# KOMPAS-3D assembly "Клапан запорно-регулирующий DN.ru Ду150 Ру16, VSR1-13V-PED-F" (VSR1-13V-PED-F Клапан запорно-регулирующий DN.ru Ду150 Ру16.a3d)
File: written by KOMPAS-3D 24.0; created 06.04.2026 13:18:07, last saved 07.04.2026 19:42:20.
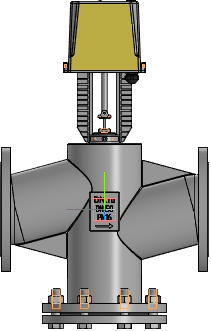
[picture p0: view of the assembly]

Document properties: Автор: R2D2; Полное имя файла: E:\Работа\Зайцев\Солянка\VSR1-13V-PED-F Клапан запорно-регулирующий DN.ru\DN150\исходные материалы\VSR1-13V-PED-F Клапан запорно-регулирующий DN.ru Ду150 Ру16.a3d

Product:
- Component [detail]: Фланец  | qty 2  | pos. 1  | Масса: 7.499952; Автор: R2D2; source file: Фланец.m3d
- Component [detail]: Фланец  | qty 1  | pos. 2  | Масса: 7.499952; Автор: R2D2; source file: Фланец.m3d
- Component [detail]: Корпус  | qty 1  | pos. 3  | Масса: 6.9; Автор: R2D2; source file: Корпус.m3d
- Component [detail]: Электропривод  | qty 1  | pos. 6  | Масса: 0.101125; Автор: R2D2; source file: Электропривод.m3d
- Component [standard]: Болт с шестигранной головкой ГОСТ Р ИСО 4014 - М20 x 80  | qty 8  | Материал: Не определено (density 1000 kg/m3); Масса: 0.2712; Раздел спецификации: Стандартные изделия; Рассекать на разрезах: no; additional columns: ГОСТ Р ИСО 4014-2013
- Component [standard]: Гайка М20-6H ГОСТ 5915-70  | qty 8  | Масса: 0.07144; Раздел спецификации: Стандартные изделия; Рассекать на разрезах: no; additional columns: М1,6-6H
- Part/product: Клапан запорно-регулирующий DN.ru Ду150 Ру16  | designation VSR1-13V-PED-F
    Масса: 56.6
    Раздел спецификации: Прочие изделия
    Примечание: D090-02896

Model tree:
1. Эскиз:1
2. Ось конической поверхности:19
3. Смещенная плоскость:19
4. ЛСК:19  (with: Плоскость XY, Плоскость ZX, Плоскость ZY, Ось X, Ось Y, Ось Z)
     Ось X. Y = -1; Ось Y. X = 1; Ось Z. Z = 1; Точка начала. Х = -45.922; Точка начала. Y = -262; Точка начала. Z = -110.866
5. Болтовое соединение
6. Массив по концентрической сетке:3  (with: Грань.Элемент выдавливания:1, Грань.Элемент вращения:1, Грань.Элемент выдавливания:8)  (8 pattern instances)
     Шаг 2 = 360; Ориентация = 2; Расстояние = -46

Expressions: VSR1-13V-PED-F; -L/2
Referenced files in E:\Работа\Зайцев\Солянка\VSR1-13V-PED-F Клапан запорно-регулирующий DN.ru\DN150\исходные материалы\: Фланец.m3d, Корпус.m3d, Электропривод.m3d
Referenced files in C:\Program Files\ASCON\KOMPAS-3D v24\Libs\PolynomLib\DATA\vault\Methods\Kompas\3D\: PLib_Bolt_1_ISO_1100.m3d, PLib_Nut_OST92_900.m3d
Referenced files in E:\Работа\Зайцев\Солянка\VSR1-13V-PED-F Клапан запорно-регулирующий DN.ru\DN20\исходные материалы\: Фланец.m3d
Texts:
  Болт с шестигранной головкой
  Крепежное изделие ГОСТ
  Программные изделия  и базы данных
  Edge1
  Edge2
  TKR3D
  Справочник стандартных изделий
  Фланец (1)
  Фланец (2)
  Фланец (3)
  Болт с шестигранной головкой ГОСТ Р ИСО 4014 - М20 x 80 (1)
  hole1
  hole2
  Гайка М20-6H ГОСТ 5915-70 (1)
  bcut1
  hcut1
  cut1
  Плоскость XY.Начало координат
  Ось Z.Начало координат
  Плоскость ZY.Начало координат
  Плоскость ZX.Начало координат
  Ось Y.Начало координат
  Plane. Начало координат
